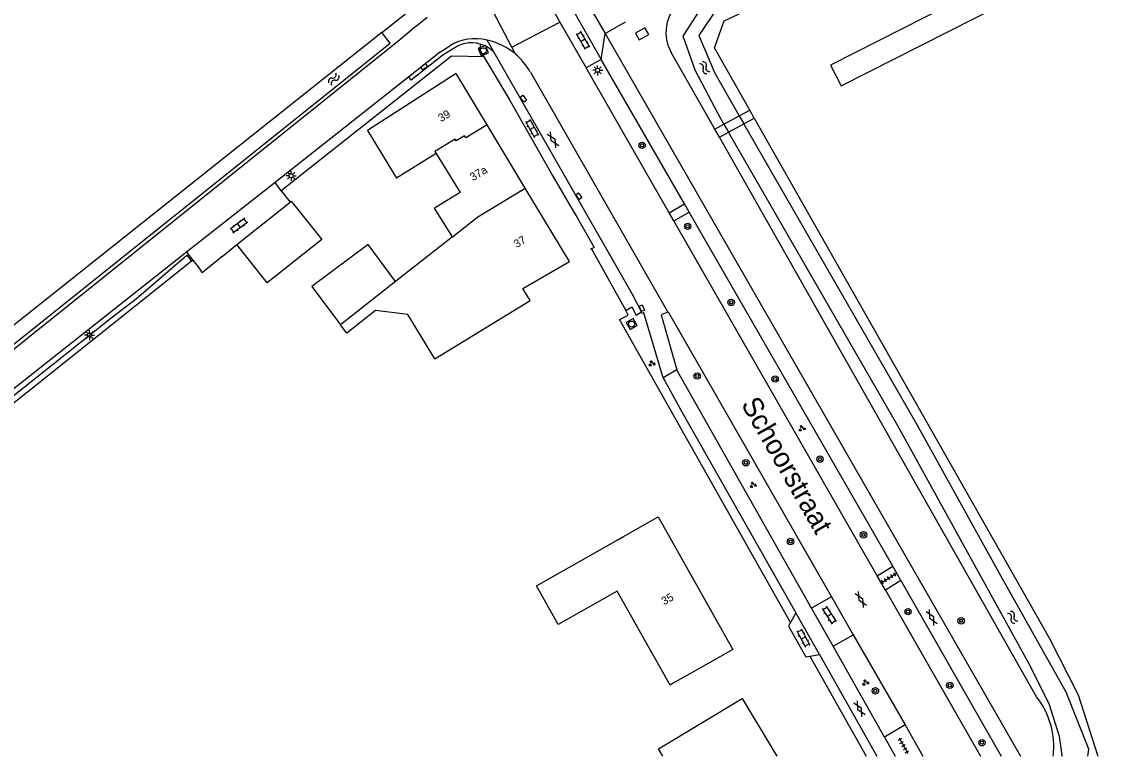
# Model space of a CAD drawing. Extents: x 134297 to 137000, y 403500 to 406000.
# Drawn here: x 136760.9 to 136897.8, y 403500 to 403591.7 of the extents above; entities that cross this region are included whole.
import ezdxf

# ---------------------------------------------------------------- set-up
doc = ezdxf.new("R2010")
doc.units = 0
for name, color, linetype in [('gg-afsc-erfafscheiding', 7, 'Continuous'), ('gg-afsc-hekwerk', 7, 'Continuous'), ('gg-afsc-muur', 7, 'Continuous'), ('gg-anno-huisnummerreeks BGT', 7, 'Continuous'), ('gg-anno-openbare ruimte label', 7, 'Continuous'), ('gg-bbg-bijgebouw', 7, 'Continuous'), ('gg-bbg-gedigitaliseerde bebouwing', 7, 'Continuous'), ('gg-bbg-gedigitaliseerde bijgebouw', 7, 'Continuous'), ('gg-bbg-hoofdgebouw', 7, 'Continuous'), ('gg-bbg-lage trafo', 7, 'Continuous'), ('gg-bbg-tussenscheiding', 7, 'Continuous'), ('gg-knt-onverhard', 7, 'Continuous'), ('gg-knt-verharding', 7, 'Continuous'), ('gg-kntw-bovenkant insteek waterloop', 7, 'Continuous'), ('gg-kntw-greppel-droge sloot', 7, 'Continuous'), ('gg-kntw-waterlijn', 7, 'Continuous'), ('gg-kwrk-kunstwerk niveau 01', 7, 'Continuous'), ('gt-grn-groengrens', 7, 'Continuous'), ('gt-grn-weggrens', 7, 'Continuous'), ('gt-symb-boom', 7, 'Continuous'), ('gt-symb-gesloten verharding', 7, 'Continuous'), ('gt-symb-groenvak', 7, 'Continuous'), ('gt-symb-klinker verharding', 7, 'Continuous'), ('gt-symb-kolk', 7, 'Continuous'), ('gt-symb-kolk center center', 7, 'Continuous'), ('gt-symb-lichtmast', 7, 'Continuous'), ('gt-symb-rioolschacht', 7, 'Continuous'), ('gt-symb-tegel verharding', 7, 'Continuous'), ('gt-symb-watersymbool', 7, 'Continuous')]:
    doc.layers.add(name, color=color, linetype=linetype)

# ---------------------------------------------------------------- blocks, each defined once
blk = doc.blocks.new('gt0-BOOM')
at = {"layer": 'gt-symb-boom'}
for radius in [0.4, 0.2]:
    blk.add_circle((0, 0), radius, dxfattribs=at)
blk = doc.blocks.new('gt0-GESVH1')
at = {"layer": 'gt-symb-gesloten verharding'}
for p, q in [((-0.99, -0.26), (0.01, 0.24)), ((0.01, -0.26), (-0.99, 0.24)), ((0.01, 0.24), (1.01, -0.26)), ((1.01, 0.24), (0.01, -0.26))]:
    blk.add_line(p, q, dxfattribs=at)
blk = doc.blocks.new('gt0-GRVAK')
at = {"layer": 'gt-symb-groenvak'}
for p, q in [((-0.11, 0.19), (-0.23, 0.24)), ((-0.18, 0.15), (0.09, 0.15)), ((-0.09, 0.21), (-0.16, 0.32)), ((-0.05, 0.21), (-0.05, 0.39)), ((0, 0.21), (0.06, 0.32)), ((0.01, 0.19), (0.13, 0.24)), ((0.26, -0.05), (0.2, 0.06)), ((0.3, -0.05), (0.3, 0.13)), ((0.35, -0.05), (0.41, 0.06)), ((-0.24, -0.23), (-0.36, -0.18)), ((-0.32, -0.26), (-0.05, -0.26)), ((-0.23, -0.21), (-0.29, -0.09)), ((-0.18, -0.2), (-0.18, -0.02)), ((-0.14, -0.21), (-0.07, -0.09)), ((-0.12, -0.23), (0, -0.18)), ((0.24, -0.07), (0.12, -0.02)), ((0.17, -0.11), (0.44, -0.11)), ((0.37, -0.07), (0.49, -0.02))]:
    blk.add_line(p, q, dxfattribs=at)
blk = doc.blocks.new('gt0-KL1')
at = {"layer": 'gt-symb-klinker verharding'}
for p, q in [((-1.15, 0.3), (1.15, 0.3)), ((-1, -0.3), (-1, 0.3)), ((-0.5, 0.3), (-0.5, 0.45)), ((0, -0.3), (0, 0.3)), ((0.5, 0.3), (0.5, 0.45)), ((1, -0.3), (1, 0.3)), ((-1.15, -0.3), (1.15, -0.3)), ((-0.5, -0.45), (-0.5, -0.3)), ((0.5, -0.45), (0.5, -0.3))]:
    blk.add_line(p, q, dxfattribs=at)
blk = doc.blocks.new('gt0-WA')
at = {"layer": 'gt-symb-watersymbool'}
for centre, start, end in [((-0.32, 0.02), 28.0725, 151.9275), ((0.43, 0.42), 208.0725, 331.9275), ((-0.32, -0.43), 28.0725, 151.9275), ((0.43, -0.03), 208.0725, 331.9275)]:
    blk.add_arc(centre, 0.425, start, end, dxfattribs=at)
blk = doc.blocks.new('gt0-TEG1')
at = {"layer": 'gt-symb-tegel verharding'}
for p, q in [((-1.12, 0), (1.12, 0)), ((-0.9, -0.25), (-0.9, 0.25)), ((-0.45, -0.25), (-0.45, 0.25)), ((0, -0.25), (0, 0.25)), ((0.45, -0.25), (0.45, 0.25)), ((0.9, -0.25), (0.9, 0.25))]:
    blk.add_line(p, q, dxfattribs=at)
blk = doc.blocks.new('gt0-RS')
at = {"layer": 'gt-symb-rioolschacht'}
blk.add_lwpolyline([(-0.5, -0.5), (0.5, -0.5), (0.5, 0.5), (-0.5, 0.5)], close=True, dxfattribs=at)
blk.add_circle((0, 0), 0.375, dxfattribs=at)
blk = doc.blocks.new('gt0-KOLKCC')
at = {"layer": 'gt-symb-kolk center center'}
blk.add_lwpolyline([(-0.38, 0.2), (0.38, 0.2), (0.38, -0.2), (-0.38, -0.2)], close=True, dxfattribs=at)
blk = doc.blocks.new('gt0-LMAST')
at = {"layer": 'gt-symb-lichtmast'}
for p, q in [((-0.18, 0.17), (-0.45, 0.44)), ((-0.01, 0.25), (-0.01, 0.62)), ((0.17, 0.17), (0.44, 0.44)), ((-0.26, 0), (-0.63, 0)), ((-0.18, -0.18), (-0.45, -0.45)), ((-0.01, -0.25), (-0.01, -0.63)), ((0.44, -0.45), (0.17, -0.18)), ((0.24, 0), (0.62, 0))]:
    blk.add_line(p, q, dxfattribs=at)
blk.add_circle((-0.01, 0), 0.25, dxfattribs=at)
blk = doc.blocks.new('gt0-KOLK')
at = {"layer": 'gt-symb-kolk'}
blk.add_lwpolyline([(0, 0), (0.38, 0), (0.38, 0.4), (-0.38, 0.4), (-0.38, 0), (0, 0)], dxfattribs=at)

msp = doc.modelspace()

# ---------------------------------------------------------------- linework, layer by layer
at = {"layer": 'gg-afsc-erfafscheiding'}
for p, q in [((136793.31, 403570.64), (136794.43, 403569.22)), ((136785.91, 403562.4), (136787.76, 403563.9)), ((136859.35, 403512.49), (136866.42, 403500))]:
    msp.add_line(p, q, dxfattribs=at)
for points in [[(136818.64, 403587.35), (136814.59, 403587.44), (136793.31, 403570.64)], [(136856.97, 403516.71), (136835.56, 403554.55), (136836.66, 403555.09)]]:
    msp.add_lwpolyline(points, dxfattribs=at)
at = {"layer": 'gg-afsc-hekwerk'}
msp.add_line((136785.91, 403562.4), (136783.43, 403560.37), dxfattribs=at)
at = {"layer": 'gg-afsc-muur'}
for p, q in [((136827.22, 403572.53), (136829.75, 403568.15)), ((136827.22, 403572.53), (136829.75, 403568.15)), ((136832.08, 403563.36), (136831.95, 403563.28))]:
    msp.add_line(p, q, dxfattribs=at)
msp.add_lwpolyline([(136830.27, 403567.29), (136832.43, 403563.56), (136832.08, 403563.36)], dxfattribs=at)
msp.add_lwpolyline([(136830.27, 403567.29), (136832.43, 403563.56), (136832.08, 403563.36)], dxfattribs=at)
at = {"layer": 'gg-bbg-bijgebouw'}
for p, q in [((136787.76, 403563.9), (136794.43, 403569.22)), ((136794.43, 403569.22), (136794.56, 403569.32)), ((136850.9, 403507.18), (136855.23, 403500))]:
    msp.add_line(p, q, dxfattribs=at)
at = {"layer": 'gg-bbg-gedigitaliseerde bebouwing'}
for p, q in [((136812.66, 403575.27), (136807.7, 403572.2)), ((136814.69, 403564.88), (136812.48, 403568.46)), ((136814.69, 403564.88), (136807.59, 403559.29)), ((136812.51, 403549.62), (136824.43, 403556.9)), ((136836.06, 403527.43), (136840.41, 403529.88)), ((136835.28, 403526.99), (136836.06, 403527.43)), ((136849.76, 403513.31), (136845.41, 403510.85)), ((136845.41, 403510.85), (136842.22, 403509.05))]:
    msp.add_line(p, q, dxfattribs=at)
for points in [[(136812.66, 403575.27), (136815.66, 403570.43), (136812.48, 403568.46)], [(136812.51, 403549.62), (136809.11, 403555.19), (136805.08, 403555.68), (136801.5, 403552.85), (136800.7, 403553.87)], [(136842.22, 403509.05), (136841.91, 403508.87), (136835.29, 403520.59), (136827.93, 403516.43), (136825.19, 403521.29), (136835.28, 403526.99)]]:
    msp.add_lwpolyline(points, dxfattribs=at)
at = {"layer": 'gg-bbg-gedigitaliseerde bijgebouw'}
for points in [[(136794.56, 403569.32), (136798.36, 403564.54), (136791.56, 403559.12), (136787.76, 403563.9)], [(136807.59, 403559.29), (136804.16, 403563.9), (136797.11, 403558.66), (136800.7, 403553.87)], [(136841, 403500), (136840.46, 403500.9), (136850.9, 403507.18)]]:
    msp.add_lwpolyline(points, dxfattribs=at)
at = {"layer": 'gg-bbg-hoofdgebouw'}
for p, q in [((136823.8, 403570.96), (136819.05, 403578.86)), ((136840.41, 403529.88), (136849.76, 403513.31))]:
    msp.add_line(p, q, dxfattribs=at)
for points in [[(136819.05, 403578.86), (136815.18, 403585.29), (136804.09, 403578.14), (136807.7, 403572.2)], [(136824.43, 403556.9), (136823.5, 403558.42), (136829.32, 403561.78), (136823.8, 403570.96)]]:
    msp.add_lwpolyline(points, dxfattribs=at)
at = {"layer": 'gg-bbg-lage trafo'}
msp.add_lwpolyline([(136838.76, 403590.99), (136837.57, 403590.34), (136838.04, 403589.49), (136839.23, 403590.14), (136838.76, 403590.99)], dxfattribs=at)
at = {"layer": 'gg-bbg-tussenscheiding'}
msp.add_line((136807.59, 403559.29), (136800.7, 403553.87), dxfattribs=at)
for points in [[(136819.05, 403578.86), (136816.38, 403577.25), (136816.22, 403577.5), (136815.16, 403576.86), (136815.03, 403577.08), (136812.49, 403575.55), (136812.66, 403575.27)], [(136814.69, 403564.88), (136817.87, 403567.39), (136823.8, 403570.96)]]:
    msp.add_lwpolyline(points, dxfattribs=at)
at = {"layer": 'gg-knt-onverhard'}
msp.add_lwpolyline([(137000, 403651.88), (136926.75, 403614.91), (136915.2, 403613.35), (136861.96, 403586.32), (136863.28, 403583.72), (136916.67, 403610.83), (136928.06, 403612.07), (137000, 403647.8)], dxfattribs=at)
at = {"layer": 'gg-knt-verharding'}
for p, q in [((136829.19, 403594.21), (136833.31, 403587.05)), ((136831.56, 403594.14), (136833.77, 403590.29)), ((136827.36, 403593.05), (136828.13, 403591.7)), ((136828.13, 403591.7), (136831.4, 403585.99)), ((136833.77, 403590.29), (136836.35, 403591.75)), ((136833.77, 403590.29), (136885.68, 403500)), ((136813.2, 403587.99), (136814.36, 403588.73)), ((136819.93, 403587.9), (136819.05, 403589.45)), ((136813.2, 403587.99), (136809.24, 403584.86)), ((136814.59, 403588.23), (136813.51, 403587.56)), ((136818.64, 403587.35), (136821.79, 403582.06)), ((136833.31, 403587.05), (136831.4, 403585.99)), ((136841.78, 403567.89), (136831.4, 403585.99)), ((136843.7, 403568.99), (136833.31, 403587.05)), ((136809.24, 403584.86), (136792.53, 403571.68)), ((136824.44, 403585.46), (136841.61, 403555.48)), ((136821.79, 403582.06), (136827.22, 403572.53)), ((136792.53, 403571.68), (136781.47, 403562.95)), ((136793.31, 403570.64), (136792.53, 403571.68)), ((136829.75, 403568.15), (136830.27, 403567.29)), ((136841.78, 403567.89), (136843.7, 403568.99)), ((136844.29, 403567.96), (136843.7, 403568.99)), ((136842.37, 403566.86), (136841.78, 403567.89)), ((136842.37, 403566.86), (136844.29, 403567.96)), ((136867.78, 403522.54), (136842.37, 403566.86)), ((136869.74, 403523.71), (136844.29, 403567.96)), ((136781.47, 403562.95), (136782.25, 403561.96)), ((136832.08, 403563.36), (136836.38, 403555.67)), ((136837.68, 403555.1), (136838.32, 403555.51)), ((136841.61, 403555.48), (136840.79, 403555.14)), ((136840.79, 403555.14), (136842.76, 403548.25)), ((136842.76, 403548.25), (136841.04, 403547.27)), ((136842.81, 403548.1), (136842.76, 403548.25)), ((136859.58, 403518.49), (136842.81, 403548.1)), ((136841.04, 403547.27), (136843.36, 403543.03)), ((136843.36, 403543.03), (136857.62, 403517.9)), ((136867.78, 403522.54), (136869.74, 403523.71)), ((136870.76, 403521.93), (136869.74, 403523.71)), ((136868.81, 403520.75), (136867.78, 403522.54)), ((136870.76, 403521.93), (136868.81, 403520.75)), ((136870.76, 403521.93), (136883.28, 403500)), ((136868.81, 403520.75), (136880.71, 403500)), ((136862.08, 403519.91), (136859.58, 403518.49)), ((136862.08, 403519.91), (136864.8, 403515.17)), ((136857.62, 403517.9), (136856.97, 403516.71)), ((136860.56, 403512.68), (136857.62, 403517.9)), ((136862.27, 403513.74), (136859.58, 403518.49)), ((136862.27, 403513.74), (136864.8, 403515.17)), ((136864.8, 403515.17), (136871.27, 403503.89)), ((136868.7, 403502.37), (136862.27, 403513.74)), ((136859.35, 403512.49), (136860.56, 403512.68)), ((136860.56, 403512.68), (136867.72, 403500)), ((136871.27, 403503.89), (136868.7, 403502.37)), ((136871.27, 403503.89), (136873.5, 403500)), ((136868.7, 403502.37), (136870.03, 403500))]:
    msp.add_line(p, q, dxfattribs=at)
for points in [[(136811.54, 403592.26), (136810.43, 403591.37), (136809.64, 403590.78)], [(136697.3, 403500), (136756.76, 403548.4), (136807.89, 403589.34), (136809.64, 403590.78)], [(136818.19, 403588.96), (136818.09, 403588.26), (136818.64, 403587.35)], [(136813.51, 403587.56), (136809.56, 403584.46), (136809.24, 403584.86)], [(136838.32, 403555.51), (136837.17, 403557.75), (136819.93, 403587.9)], [(136781.47, 403562.95), (136758.93, 403545.15), (136735.8, 403526.32)], [(136782.25, 403561.96), (136782.91, 403561.11), (136783.43, 403560.37)], [(136836.38, 403555.67), (136837.12, 403556.13), (136837.68, 403555.1)], [(136841.04, 403547.27), (136838.64, 403555.38), (136838.42, 403555.3), (136838.32, 403555.51)], [(136841.61, 403555.48), (136841.66, 403555.5), (136862.08, 403519.91)], [(136856.97, 403516.71), (136856.71, 403516.24), (136858.87, 403512.42), (136859.35, 403512.49)]]:
    msp.add_lwpolyline(points, dxfattribs=at)
for centre, radius, start, end in [((136817.53, 403583.69), 5.95, 75.2439, 122.2319), ((136817.09, 403585.17), 3.94, 73.8235, 129.28), ((136817.06, 403585.13), 3.99, 43.8936, 73.6217), ((136817.32, 403581.48), 8.15, 49.9366, 77.7697), ((136817.33, 403581.48), 8.14, 29.2257, 49.9956)]:
    msp.add_arc(centre, radius, start, end, dxfattribs=at)
at = {"layer": 'gg-kntw-bovenkant insteek waterloop'}
for p, q in [((136805.88, 403590.4), (136724.61, 403525.83)), ((136847.48, 403578.34), (136842.05, 403587.91)), ((136887.7, 403507.42), (136848.06, 403577.32))]:
    msp.add_line(p, q, dxfattribs=at)
for points in [[(136851.86, 403580.72), (136847.45, 403588.5), (136848.68, 403591.88), (136851, 403592.94)], [(136724.61, 403525.83), (136725.76, 403524.22), (136806.91, 403589.07), (136805.88, 403590.4)], [(136852.43, 403579.71), (136889.31, 403514.71), (136892.9, 403507.64), (136895.38, 403500)]]:
    msp.add_lwpolyline(points, dxfattribs=at)
for centre, radius, start, end in [((136846.46, 403590.41), 5.07, 121.1024, 209.5638), ((136879.75, 403501.19), 10.1, 353.2161, 38.0454)]:
    msp.add_arc(centre, radius, start, end, dxfattribs=at)
at = {"layer": 'gg-kntw-greppel-droge sloot'}
for points in [[(136736.13, 403524.67), (136735.96, 403526.1), (136756.67, 403542.55), (136772.21, 403554.89), (136775.21, 403557.18), (136781.5, 403562.57), (136782.1, 403561.84)], [(136782.1, 403561.84), (136779.33, 403559.61), (136757.22, 403541.99), (136744.33, 403531.75), (136738.27, 403526.63), (136736.13, 403524.67)]]:
    msp.add_lwpolyline(points, dxfattribs=at)
at = {"layer": 'gg-kntw-waterlijn'}
for p, q in [((136850.52, 403580), (136851.11, 403578.98)), ((136848.64, 403578.97), (136849.22, 403577.96))]:
    msp.add_line(p, q, dxfattribs=at)
for points in [[(136848.64, 403578.97), (136847.95, 403580.17), (136845.03, 403585.68), (136843.54, 403589.96), (136846.41, 403594.39), (136849.34, 403595.88)], [(136850.22, 403594.31), (136847.63, 403593.18), (136845.5, 403590.03), (136847.48, 403585.31), (136850.52, 403580)], [(136890.86, 403500), (136890.9, 403500.12), (136890.56, 403502.44), (136889.26, 403506.54), (136886.65, 403511.75), (136870.35, 403541.25), (136849.22, 403577.96)], [(136894.12, 403500), (136894.24, 403500.85), (136891.41, 403507.97), (136883.44, 403522.13), (136872.8, 403541.4), (136851.11, 403578.98)]]:
    msp.add_lwpolyline(points, dxfattribs=at)
at = {"layer": 'gg-kwrk-kunstwerk niveau 01'}
for p, q in [((136850.52, 403580), (136851.86, 403580.72)), ((136852.43, 403579.71), (136851.86, 403580.72)), ((136848.64, 403578.97), (136850.52, 403580)), ((136851.11, 403578.98), (136852.43, 403579.71)), ((136847.48, 403578.34), (136848.64, 403578.97)), ((136848.06, 403577.32), (136847.48, 403578.34)), ((136848.06, 403577.32), (136849.22, 403577.96)), ((136849.22, 403577.96), (136851.11, 403578.98))]:
    msp.add_line(p, q, dxfattribs=at)
at = {"layer": 'gt-grn-groengrens'}
for p, q in [((136805.88, 403590.4), (136810.5, 403594.07)), ((136782.1, 403561.84), (136782.25, 403561.96)), ((136836.66, 403555.09), (136836.38, 403555.67))]:
    msp.add_line(p, q, dxfattribs=at)
at = {"layer": 'gt-grn-weggrens'}
for p, q in [((136822.12, 403588.57), (136815.17, 403601.88)), ((136822.12, 403588.57), (136828.13, 403591.7)), ((136833.31, 403587.05), (136833.77, 403590.29)), ((136822.57, 403587.72), (136822.12, 403588.57))]:
    msp.add_line(p, q, dxfattribs=at)

# ---------------------------------------------------------------- block references
at = {"layer": 'gt-symb-boom'}
for p in [(136838.4, 403576.31), (136844.1, 403566.18), (136849.54, 403556.68), (136845.29, 403547.49), (136855.03, 403547.11), (136851.37, 403536.65), (136860.64, 403537.1), (136856.96, 403526.81), (136866.07, 403527.64), (136871.64, 403518.04), (136878.28, 403516.9), (136867.56, 403508.15), (136876.86, 403508.84), (136880.89, 403501.67)]:
    msp.add_blockref('gt0-BOOM', p, dxfattribs=at)
at = {"layer": 'gt-symb-gesloten verharding'}
for p, rotation in [((136827.27, 403577), -58.99693247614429), ((136865.75, 403519.57), -59.99927222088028), ((136874.58, 403517.29), 117.97472992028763), ((136865.57, 403505.89), 117.97472992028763)]:
    msp.add_blockref('gt0-GESVH1', p, dxfattribs=dict(at, rotation=rotation))
at = {"layer": 'gt-symb-groenvak'}
for p in [(136839.61, 403549.04), (136858.37, 403540.94), (136852.27, 403533.87), (136866.32, 403509.18)]:
    msp.add_blockref('gt0-GRVAK', p, dxfattribs=at)
at = {"layer": 'gt-symb-klinker verharding'}
for p, rotation in [((136831.03, 403589.41), 120.00072778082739), ((136824.65, 403578.44), -60.97323370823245), ((136788.01, 403566.27), -143.70304105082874), ((136861.78, 403517.62), -57.454106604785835), ((136858.56, 403514.76), -62.48693881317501)]:
    msp.add_blockref('gt0-KL1', p, dxfattribs=dict(at, rotation=rotation))
at = {"layer": 'gt-symb-kolk', "rotation": -141.71450389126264}
msp.add_blockref('gt0-KOLK', (136811.03, 403586.28), dxfattribs=at)
at = {"layer": 'gt-symb-kolk center center'}
for p, rotation in [((136823.57, 403582.13), 126.01052540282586), ((136830.5, 403569.95), 128.25701687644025), ((136838.37, 403555.96), 114.0265065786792)]:
    msp.add_blockref('gt0-KOLKCC', p, dxfattribs=dict(at, rotation=rotation))
at = {"layer": 'gt-symb-lichtmast'}
for p in [(136832.86, 403585.68), (136794.55, 403572.51), (136769.35, 403552.6)]:
    msp.add_blockref('gt0-LMAST', p, dxfattribs=at)
at = {"layer": 'gt-symb-rioolschacht'}
for p, rotation in [((136818.57, 403588.12), 22.386365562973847), ((136837.09, 403553.98), -60.4612177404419)]:
    msp.add_blockref('gt0-RS', p, dxfattribs=dict(at, rotation=rotation))
at = {"layer": 'gt-symb-tegel verharding'}
for p, rotation in [((136869.22, 403522.22), 31.671318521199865), ((136871.07, 403501.32), -60.92313646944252)]:
    msp.add_blockref('gt0-TEG1', p, dxfattribs=dict(at, rotation=rotation))
at = {"layer": 'gt-symb-watersymbool'}
for p, rotation in [((136846.25, 403585.96), 126.9958977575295), ((136799.9, 403584.61), -126.99589775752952), ((136884.74, 403517.3), 126.99589775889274)]:
    msp.add_blockref('gt0-WA', p, dxfattribs=dict(at, rotation=rotation))

# ---------------------------------------------------------------- texts
at = {"layer": 'gg-anno-huisnummerreeks BGT'}
for s, rotation, p in [('39', 31, (136813.28, 403579.18)), ('37a', 31, (136817.26, 403571.82)), ('37', 31, (136822.74, 403563.46)), ('35', 29.4, (136841.16, 403518.83))]:
    msp.add_text(s, height=1, rotation=rotation, dxfattribs=at).set_placement(p)
at = {"layer": 'gg-anno-openbare ruimte label'}
msp.add_text('Schoorstraat', height=2.5, rotation=299.9, dxfattribs=at).set_placement((136850.72, 403543.96))

doc.saveas('drawing.dxf')
